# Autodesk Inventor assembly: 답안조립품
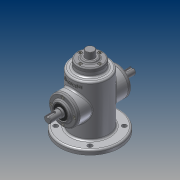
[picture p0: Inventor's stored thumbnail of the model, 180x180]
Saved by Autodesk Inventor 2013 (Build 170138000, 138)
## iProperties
Created: 2014-12
Part Number: 답안조립품
Document SubType Name: Assembly
Designer: CAD-B16
Author: CAD-B16
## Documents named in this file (12)
- C:\Users\CAD-B16\Desktop\441228V1008\답안조립품.iam
- C:\Users\CAD-B16\Desktop\441228V1008\1-본체.ipt
- C:\Users\CAD-B16\Desktop\441228V1008\2-편심축.ipt
- C:\Users\CAD-B16\Desktop\441228V1008\M3x0.5x8.ipt
- M3x0.5.ipt
- C:\Users\CAD-B16\Desktop\441228V1008\베어링 6002.ipt
- 베어링 6002.ipt
- C:\Users\CAD-B16\Desktop\441228V1008\상단커버.ipt
- C:\Users\CAD-B16\Desktop\441228V1008\슬라이드.ipt
- C:\Users\CAD-B16\Desktop\441228V1008\오일실.ipt
- 오일실.ipt
- C:\Users\CAD-B16\Desktop\441228V1008\커버.ipt
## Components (14 placed, 3 different names)
1. 1-본체:1 — 각도:2, 각도:3
2. 2-편심축:1
3. M3x0.5:3 — 각도:2
4. M3x0.5:4
5. M3x0.5:5
6. M3x0.5:6
7. M3x0.5:2 — 각도:3
8. M3x0.5:7
9. M3x0.5:8
10. M3x0.5:9
11. M3x0.5:1 — 각도:4
12. M3x0.5:10
13. M3x0.5:11
14. M3x0.5:12
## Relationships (3: Angle 3)
- 각도:2 [Angle]: 1-본체:1 ↔ M3x0.5:3
- 각도:3 [Angle]: 1-본체:1 ↔ M3x0.5:2
- 각도:4 [Angle]: M3x0.5:1
